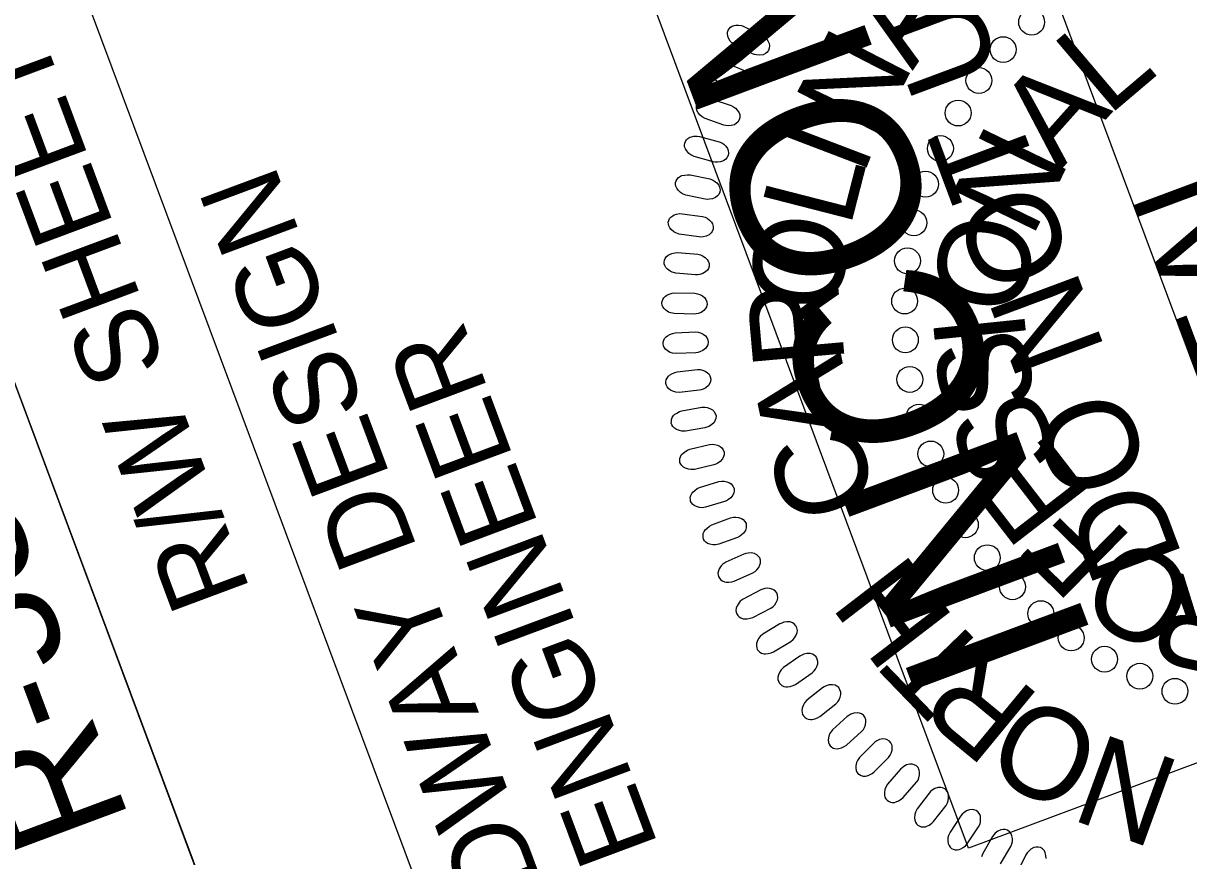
# Model space of a CAD drawing. Extents: x 477774 to 479389, y 493760 to 495720.
# Drawn here: x 477869.3 to 477941.5, y 495190.7 to 495242.3 of the extents above; entities that cross this region are included whole.
import ezdxf

# ---------------------------------------------------------------- set-up
doc = ezdxf.new("R2010")
doc.units = 0
for name, color, linetype in [('Sheet Data Field CELL', 7, 'Continuous'), ('Sheet PE Seal Cell', 7, 'Continuous'), ('Sheet Plan CELL', 7, 'Continuous'), ('Sheet Sticker Incomplete CELL', 7, 'Continuous')]:
    doc.layers.add(name, color=color, linetype=linetype)

msp = doc.modelspace()

# ---------------------------------------------------------------- linework, layer by layer
at = {"layer": 'Sheet PE Seal Cell'}
for points in [[(477914.47, 495240.395), (477913.371, 495240.94), (477913.191, 495241.071), (477913.088, 495241.179), (477912.986, 495241.355), (477912.931, 495241.491), (477912.91, 495241.626), (477912.92, 495241.738), (477912.952, 495241.848), (477913.02, 495241.939), (477913.1, 495242.033), (477913.2, 495242.101), (477913.335, 495242.15), (477913.434, 495242.168), (477913.597, 495242.162), (477913.785, 495242.136), (477913.938, 495242.085), (477915.067, 495241.534), (477915.209, 495241.439), (477915.314, 495241.337), (477915.417, 495241.186), (477915.493, 495241.023), (477915.522, 495240.9), (477915.505, 495240.733), (477915.457, 495240.59), (477915.355, 495240.474), (477915.264, 495240.402), (477915.118, 495240.333), (477914.913, 495240.301), (477914.722, 495240.32), (477914.592, 495240.351)], [(477913.494, 495238.169), (477912.362, 495238.643), (477912.174, 495238.762), (477912.065, 495238.865), (477911.952, 495239.034), (477911.889, 495239.166), (477911.858, 495239.3), (477911.862, 495239.412), (477911.887, 495239.523), (477911.949, 495239.619), (477912.023, 495239.717), (477912.118, 495239.791), (477912.251, 495239.849), (477912.348, 495239.873), (477912.512, 495239.877), (477912.7, 495239.863), (477912.856, 495239.822), (477914.018, 495239.343), (477914.165, 495239.257), (477914.277, 495239.161), (477914.389, 495239.017), (477914.475, 495238.86), (477914.511, 495238.739), (477914.505, 495238.571), (477914.466, 495238.425), (477914.371, 495238.303), (477914.285, 495238.226), (477914.144, 495238.147), (477913.941, 495238.103), (477913.75, 495238.11), (477913.619, 495238.133)], [(477912.695, 495235.98), (477911.536, 495236.382), (477911.341, 495236.489), (477911.226, 495236.584), (477911.102, 495236.746), (477911.03, 495236.874), (477910.992, 495237.006), (477910.989, 495237.117), (477911.007, 495237.231), (477911.062, 495237.329), (477911.13, 495237.433), (477911.221, 495237.512), (477911.349, 495237.578), (477911.444, 495237.609), (477911.608, 495237.622), (477911.797, 495237.621), (477911.955, 495237.59), (477913.144, 495237.184), (477913.297, 495237.108), (477913.415, 495237.019), (477913.535, 495236.882), (477913.631, 495236.73), (477913.675, 495236.612), (477913.68, 495236.444), (477913.649, 495236.297), (477913.562, 495236.168), (477913.481, 495236.086), (477913.345, 495235.999), (477913.146, 495235.942), (477912.954, 495235.937), (477912.822, 495235.952)], [(477912.03, 495233.709), (477910.849, 495234.038), (477910.647, 495234.133), (477910.526, 495234.221), (477910.393, 495234.374), (477910.313, 495234.497), (477910.266, 495234.626), (477910.256, 495234.739), (477910.267, 495234.852), (477910.316, 495234.954), (477910.377, 495235.061), (477910.463, 495235.146), (477910.587, 495235.22), (477910.68, 495235.257), (477910.842, 495235.282), (477911.031, 495235.291), (477911.191, 495235.27), (477912.403, 495234.94), (477912.561, 495234.873), (477912.683, 495234.792), (477912.813, 495234.663), (477912.918, 495234.518), (477912.968, 495234.402), (477912.984, 495234.235), (477912.963, 495234.086), (477912.885, 495233.952), (477912.808, 495233.865), (477912.678, 495233.769), (477912.483, 495233.7), (477912.292, 495233.683), (477912.159, 495233.689)], [(477911.536, 495231.391), (477910.337, 495231.645), (477910.13, 495231.727), (477910.004, 495231.807), (477909.861, 495231.951), (477909.774, 495232.069), (477909.719, 495232.195), (477909.702, 495232.306), (477909.706, 495232.42), (477909.748, 495232.526), (477909.803, 495232.636), (477909.882, 495232.726), (477910.002, 495232.808), (477910.092, 495232.85), (477910.253, 495232.885), (477910.441, 495232.906), (477910.601, 495232.895), (477911.832, 495232.642), (477911.993, 495232.585), (477912.12, 495232.512), (477912.258, 495232.392), (477912.372, 495232.253), (477912.43, 495232.142), (477912.456, 495231.975), (477912.444, 495231.825), (477912.374, 495231.687), (477912.303, 495231.595), (477912.18, 495231.491), (477911.989, 495231.41), (477911.8, 495231.381), (477911.666, 495231.379)], [(477911.146, 495229.048), (477909.933, 495229.226), (477909.721, 495229.295), (477909.59, 495229.367), (477909.439, 495229.503), (477909.345, 495229.615), (477909.282, 495229.737), (477909.257, 495229.847), (477909.254, 495229.96), (477909.29, 495230.068), (477909.337, 495230.182), (477909.411, 495230.277), (477909.525, 495230.366), (477909.613, 495230.414), (477909.77, 495230.459), (477909.957, 495230.492), (477910.118, 495230.491), (477911.363, 495230.316), (477911.527, 495230.269), (477911.659, 495230.204), (477911.803, 495230.093), (477911.925, 495229.961), (477911.99, 495229.854), (477912.027, 495229.689), (477912.025, 495229.539), (477911.964, 495229.396), (477911.899, 495229.3), (477911.782, 495229.189), (477911.597, 495229.095), (477911.409, 495229.055), (477911.276, 495229.044)], [(477910.938, 495226.703), (477909.715, 495226.805), (477909.5, 495226.86), (477909.365, 495226.924), (477909.205, 495227.05), (477909.104, 495227.155), (477909.034, 495227.274), (477909.003, 495227.382), (477908.992, 495227.495), (477909.022, 495227.605), (477909.061, 495227.722), (477909.129, 495227.821), (477909.238, 495227.917), (477909.322, 495227.97), (477909.477, 495228.025), (477909.66, 495228.069), (477909.821, 495228.079), (477911.074, 495227.982), (477911.241, 495227.946), (477911.377, 495227.889), (477911.529, 495227.787), (477911.658, 495227.663), (477911.73, 495227.56), (477911.777, 495227.398), (477911.784, 495227.248), (477911.732, 495227.103), (477911.673, 495227.002), (477911.563, 495226.884), (477911.385, 495226.779), (477911.2, 495226.726), (477911.069, 495226.708)], [(477910.846, 495224.277), (477909.62, 495224.301), (477909.401, 495224.343), (477909.263, 495224.398), (477909.095, 495224.514), (477908.988, 495224.613), (477908.91, 495224.727), (477908.873, 495224.832), (477908.854, 495224.945), (477908.877, 495225.056), (477908.909, 495225.175), (477908.972, 495225.279), (477909.073, 495225.382), (477909.154, 495225.44), (477909.305, 495225.504), (477909.485, 495225.561), (477909.645, 495225.58), (477910.902, 495225.562), (477911.071, 495225.535), (477911.21, 495225.488), (477911.367, 495225.395), (477911.505, 495225.281), (477911.583, 495225.182), (477911.639, 495225.023), (477911.656, 495224.873), (477911.613, 495224.725), (477911.562, 495224.621), (477911.459, 495224.496), (477911.287, 495224.38), (477911.107, 495224.316), (477910.976, 495224.289)], [(477910.957, 495221.881), (477909.731, 495221.828), (477909.51, 495221.856), (477909.368, 495221.903), (477909.194, 495222.007), (477909.081, 495222.1), (477908.996, 495222.208), (477908.952, 495222.311), (477908.927, 495222.422), (477908.942, 495222.535), (477908.967, 495222.656), (477909.022, 495222.764), (477909.117, 495222.872), (477909.194, 495222.935), (477909.341, 495223.009), (477909.518, 495223.076), (477909.676, 495223.105), (477910.931, 495223.166), (477911.102, 495223.152), (477911.243, 495223.112), (477911.407, 495223.03), (477911.551, 495222.923), (477911.634, 495222.83), (477911.701, 495222.676), (477911.727, 495222.527), (477911.694, 495222.376), (477911.648, 495222.27), (477911.555, 495222.138), (477911.39, 495222.012), (477911.214, 495221.936), (477911.085, 495221.901)], [(477911.16, 495219.555), (477909.941, 495219.426), (477909.719, 495219.44), (477909.574, 495219.477), (477909.393, 495219.571), (477909.274, 495219.656), (477909.183, 495219.759), (477909.133, 495219.859), (477909.1, 495219.968), (477909.109, 495220.082), (477909.126, 495220.204), (477909.174, 495220.314), (477909.263, 495220.428), (477909.335, 495220.496), (477909.477, 495220.579), (477909.649, 495220.658), (477909.806, 495220.698), (477911.055, 495220.837), (477911.226, 495220.832), (477911.369, 495220.802), (477911.537, 495220.73), (477911.688, 495220.633), (477911.778, 495220.545), (477911.854, 495220.395), (477911.889, 495220.249), (477911.865, 495220.096), (477911.827, 495219.987), (477911.741, 495219.85), (477911.585, 495219.713), (477911.413, 495219.627), (477911.288, 495219.584)], [(477911.523, 495217.23), (477910.314, 495217.024), (477910.091, 495217.024), (477909.945, 495217.053), (477909.759, 495217.135), (477909.634, 495217.212), (477909.537, 495217.309), (477909.48, 495217.405), (477909.441, 495217.513), (477909.442, 495217.627), (477909.452, 495217.75), (477909.493, 495217.863), (477909.574, 495217.983), (477909.642, 495218.055), (477909.779, 495218.146), (477909.946, 495218.236), (477910.1, 495218.285), (477911.337, 495218.503), (477911.508, 495218.508), (477911.653, 495218.488), (477911.825, 495218.426), (477911.982, 495218.339), (477912.077, 495218.257), (477912.162, 495218.112), (477912.207, 495217.968), (477912.192, 495217.814), (477912.161, 495217.702), (477912.084, 495217.561), (477911.937, 495217.414), (477911.771, 495217.317), (477911.648, 495217.266)], [(477912.072, 495214.938), (477910.878, 495214.657), (477910.656, 495214.643), (477910.509, 495214.662), (477910.318, 495214.732), (477910.188, 495214.802), (477910.085, 495214.893), (477910.022, 495214.985), (477909.977, 495215.09), (477909.971, 495215.204), (477909.973, 495215.326), (477910.007, 495215.442), (477910.08, 495215.567), (477910.144, 495215.643), (477910.274, 495215.744), (477910.436, 495215.842), (477910.585, 495215.901), (477911.807, 495216.196), (477911.977, 495216.213), (477912.123, 495216.202), (477912.299, 495216.151), (477912.461, 495216.074), (477912.56, 495215.998), (477912.655, 495215.858), (477912.709, 495215.718), (477912.704, 495215.563), (477912.68, 495215.45), (477912.612, 495215.303), (477912.474, 495215.147), (477912.314, 495215.041), (477912.195, 495214.982)], [(477912.735, 495212.664), (477911.56, 495212.308), (477911.34, 495212.28), (477911.191, 495212.29), (477910.996, 495212.348), (477910.863, 495212.409), (477910.754, 495212.493), (477910.686, 495212.582), (477910.634, 495212.684), (477910.621, 495212.796), (477910.615, 495212.92), (477910.642, 495213.037), (477910.706, 495213.166), (477910.766, 495213.246), (477910.889, 495213.354), (477911.044, 495213.463), (477911.189, 495213.531), (477912.391, 495213.902), (477912.559, 495213.931), (477912.706, 495213.928), (477912.884, 495213.888), (477913.05, 495213.821), (477913.155, 495213.752), (477913.258, 495213.619), (477913.321, 495213.481), (477913.326, 495213.327), (477913.308, 495213.212), (477913.249, 495213.061), (477913.122, 495212.898), (477912.97, 495212.781), (477912.854, 495212.715)], [(477913.535, 495210.444), (477912.386, 495210.015), (477912.167, 495209.974), (477912.017, 495209.974), (477911.819, 495210.02), (477911.683, 495210.073), (477911.569, 495210.15), (477911.495, 495210.234), (477911.437, 495210.332), (477911.417, 495210.444), (477911.403, 495210.566), (477911.422, 495210.685), (477911.479, 495210.818), (477911.533, 495210.902), (477911.65, 495211.017), (477911.797, 495211.137), (477911.939, 495211.213), (477913.113, 495211.659), (477913.28, 495211.698), (477913.427, 495211.704), (477913.607, 495211.676), (477913.778, 495211.62), (477913.886, 495211.556), (477913.997, 495211.43), (477914.068, 495211.297), (477914.083, 495211.143), (477914.073, 495211.028), (477914.024, 495210.873), (477913.906, 495210.702), (477913.762, 495210.577), (477913.651, 495210.503)], [(477913.933, 495209.402), (477912.813, 495208.902), (477912.628, 495208.779), (477912.522, 495208.674), (477912.412, 495208.502), (477912.352, 495208.369), (477912.325, 495208.234), (477912.331, 495208.123), (477912.359, 495208.012), (477912.423, 495207.918), (477912.498, 495207.821), (477912.595, 495207.749), (477912.73, 495207.694), (477912.827, 495207.673), (477912.991, 495207.672), (477913.179, 495207.69), (477913.334, 495207.735), (477914.484, 495208.24), (477914.63, 495208.33), (477914.739, 495208.428), (477914.849, 495208.574), (477914.93, 495208.734), (477914.964, 495208.855), (477914.954, 495209.023), (477914.912, 495209.168), (477914.814, 495209.288), (477914.726, 495209.363), (477914.583, 495209.438), (477914.38, 495209.479), (477914.188, 495209.467), (477914.057, 495209.442)], [(477914.976, 495207.189), (477913.889, 495206.619), (477913.712, 495206.485), (477913.613, 495206.373), (477913.514, 495206.195), (477913.463, 495206.058), (477913.444, 495205.922), (477913.457, 495205.811), (477913.491, 495205.702), (477913.561, 495205.612), (477913.643, 495205.52), (477913.745, 495205.455), (477913.882, 495205.409), (477913.98, 495205.393), (477914.144, 495205.403), (477914.331, 495205.433), (477914.482, 495205.487), (477915.599, 495206.064), (477915.739, 495206.162), (477915.842, 495206.267), (477915.941, 495206.42), (477916.013, 495206.584), (477916.038, 495206.707), (477916.019, 495206.874), (477915.967, 495207.016), (477915.862, 495207.13), (477915.769, 495207.2), (477915.622, 495207.266), (477915.417, 495207.293), (477915.226, 495207.269), (477915.098, 495207.235)], [(477916.153, 495205.087), (477915.105, 495204.451), (477914.937, 495204.305), (477914.844, 495204.188), (477914.757, 495204.003), (477914.714, 495203.864), (477914.704, 495203.727), (477914.724, 495203.617), (477914.765, 495203.51), (477914.84, 495203.424), (477914.928, 495203.338), (477915.033, 495203.279), (477915.173, 495203.241), (477915.273, 495203.232), (477915.435, 495203.252), (477915.619, 495203.294), (477915.768, 495203.357), (477916.846, 495204.003), (477916.979, 495204.11), (477917.075, 495204.221), (477917.165, 495204.38), (477917.226, 495204.549), (477917.244, 495204.673), (477917.214, 495204.839), (477917.153, 495204.976), (477917.041, 495205.084), (477916.945, 495205.147), (477916.794, 495205.204), (477916.587, 495205.219), (477916.398, 495205.183), (477916.272, 495205.141)], [(477917.402, 495203.092), (477916.395, 495202.391), (477916.237, 495202.235), (477916.151, 495202.112), (477916.077, 495201.923), (477916.042, 495201.781), (477916.041, 495201.643), (477916.067, 495201.534), (477916.115, 495201.431), (477916.196, 495201.35), (477916.289, 495201.27), (477916.398, 495201.218), (477916.539, 495201.189), (477916.639, 495201.185), (477916.8, 495201.216), (477916.981, 495201.269), (477917.125, 495201.342), (477918.161, 495202.054), (477918.287, 495202.169), (477918.376, 495202.286), (477918.456, 495202.451), (477918.506, 495202.622), (477918.516, 495202.747), (477918.476, 495202.911), (477918.407, 495203.045), (477918.289, 495203.145), (477918.188, 495203.202), (477918.033, 495203.249), (477917.826, 495203.25), (477917.64, 495203.203), (477917.517, 495203.154)], [(477918.799, 495201.123), (477917.839, 495200.36), (477917.69, 495200.195), (477917.613, 495200.067), (477917.55, 495199.874), (477917.524, 495199.729), (477917.532, 495199.592), (477917.565, 495199.485), (477917.62, 495199.385), (477917.705, 495199.309), (477917.803, 495199.235), (477917.914, 495199.189), (477918.058, 495199.169), (477918.158, 495199.172), (477918.317, 495199.212), (477918.494, 495199.277), (477918.634, 495199.359), (477919.622, 495200.134), (477919.741, 495200.258), (477919.822, 495200.379), (477919.892, 495200.549), (477919.931, 495200.723), (477919.933, 495200.849), (477919.882, 495201.01), (477919.805, 495201.139), (477919.681, 495201.231), (477919.576, 495201.282), (477919.42, 495201.32), (477919.212, 495201.308), (477919.03, 495201.249), (477918.91, 495201.192)], [(477920.334, 495199.347), (477919.423, 495198.525), (477919.285, 495198.35), (477919.216, 495198.218), (477919.165, 495198.021), (477919.149, 495197.875), (477919.165, 495197.739), (477919.205, 495197.634), (477919.266, 495197.538), (477919.356, 495197.468), (477919.458, 495197.399), (477919.573, 495197.361), (477919.717, 495197.35), (477919.816, 495197.359), (477919.972, 495197.41), (477920.145, 495197.486), (477920.279, 495197.575), (477921.217, 495198.412), (477921.328, 495198.542), (477921.401, 495198.669), (477921.46, 495198.842), (477921.489, 495199.019), (477921.483, 495199.145), (477921.422, 495199.301), (477921.336, 495199.426), (477921.207, 495199.509), (477921.1, 495199.554), (477920.94, 495199.582), (477920.734, 495199.558), (477920.556, 495199.487), (477920.44, 495199.422)], [(477921.948, 495197.689), (477921.09, 495196.812), (477920.964, 495196.629), (477920.904, 495196.492), (477920.865, 495196.293), (477920.858, 495196.146), (477920.883, 495196.011), (477920.93, 495195.909), (477920.996, 495195.817), (477921.09, 495195.752), (477921.196, 495195.69), (477921.313, 495195.66), (477921.458, 495195.658), (477921.556, 495195.673), (477921.709, 495195.733), (477921.877, 495195.82), (477922.005, 495195.918), (477922.888, 495196.811), (477922.991, 495196.948), (477923.056, 495197.08), (477923.103, 495197.256), (477923.121, 495197.435), (477923.107, 495197.559), (477923.037, 495197.712), (477922.944, 495197.831), (477922.809, 495197.907), (477922.699, 495197.944), (477922.539, 495197.962), (477922.335, 495197.925), (477922.161, 495197.843), (477922.049, 495197.771)], [(477923.627, 495196.092), (477922.826, 495195.162), (477922.71, 495194.972), (477922.659, 495194.832), (477922.633, 495194.631), (477922.635, 495194.484), (477922.668, 495194.35), (477922.721, 495194.252), (477922.794, 495194.163), (477922.891, 495194.105), (477923.001, 495194.05), (477923.12, 495194.027), (477923.264, 495194.034), (477923.362, 495194.056), (477923.51, 495194.125), (477923.673, 495194.222), (477923.794, 495194.328), (477924.62, 495195.276), (477924.714, 495195.418), (477924.77, 495195.553), (477924.807, 495195.732), (477924.813, 495195.912), (477924.792, 495196.036), (477924.712, 495196.184), (477924.612, 495196.296), (477924.472, 495196.364), (477924.36, 495196.394), (477924.199, 495196.402), (477923.998, 495196.351), (477923.829, 495196.259), (477923.722, 495196.18)], [(477925.402, 495194.601), (477924.661, 495193.624), (477924.558, 495193.426), (477924.516, 495193.283), (477924.502, 495193.08), (477924.514, 495192.934), (477924.555, 495192.803), (477924.614, 495192.708), (477924.692, 495192.624), (477924.793, 495192.572), (477924.906, 495192.524), (477925.026, 495192.508), (477925.169, 495192.525), (477925.265, 495192.552), (477925.41, 495192.631), (477925.565, 495192.738), (477925.68, 495192.852), (477926.445, 495193.849), (477926.529, 495193.997), (477926.578, 495194.136), (477926.602, 495194.317), (477926.598, 495194.496), (477926.569, 495194.618), (477926.479, 495194.761), (477926.372, 495194.867), (477926.229, 495194.926), (477926.115, 495194.949), (477925.954, 495194.947), (477925.756, 495194.883), (477925.594, 495194.78), (477925.492, 495194.696)], [(477927.371, 495193.201), (477926.693, 495192.178), (477926.602, 495191.975), (477926.568, 495191.83), (477926.568, 495191.626), (477926.589, 495191.481), (477926.638, 495191.353), (477926.704, 495191.261), (477926.786, 495191.183), (477926.89, 495191.138), (477927.006, 495191.096), (477927.127, 495191.088), (477927.269, 495191.114), (477927.363, 495191.147), (477927.502, 495191.235), (477927.651, 495191.351), (477927.758, 495191.472), (477928.459, 495192.515), (477928.533, 495192.669), (477928.574, 495192.81), (477928.587, 495192.992), (477928.571, 495193.17), (477928.534, 495193.291), (477928.436, 495193.427), (477928.322, 495193.527), (477928.176, 495193.576), (477928.061, 495193.592), (477927.9, 495193.58), (477927.707, 495193.504), (477927.551, 495193.392), (477927.454, 495193.3)]]:
    msp.add_lwpolyline(points, close=True, dxfattribs=at)
for points in [[(477929.825, 495190.224), (477930.459, 495191.308), (477930.524, 495191.467), (477930.555, 495191.61), (477930.557, 495191.793), (477930.529, 495191.97), (477930.485, 495192.088), (477930.379, 495192.218), (477930.259, 495192.31), (477930.109, 495192.349), (477929.994, 495192.359), (477929.834, 495192.336), (477929.646, 495192.249), (477929.498, 495192.127), (477929.407, 495192.029), (477929.329, 495191.925), (477928.717, 495190.861), (477928.64, 495190.653)], [(477932.638, 495190.551), (477932.629, 495190.733), (477932.591, 495190.909), (477932.539, 495191.024), (477932.425, 495191.147), (477932.299, 495191.231), (477932.148, 495191.261), (477932.032, 495191.263), (477931.874, 495191.231), (477931.692, 495191.132), (477931.552, 495191), (477931.467, 495190.898), (477931.397, 495190.788), (477930.852, 495189.689)]]:
    msp.add_lwpolyline(points, dxfattribs=at)
for centre in [(477931.747, 495242.35), (477929.98, 495240.652), (477928.484, 495238.735), (477927.193, 495236.724), (477926.098, 495234.531), (477925.18, 495232.318), (477924.457, 495229.924), (477924.06, 495227.567), (477923.883, 495225.079), (477923.929, 495222.674), (477924.204, 495220.227), (477924.777, 495217.891), (477925.5, 495215.611), (477926.423, 495213.364), (477927.645, 495211.227), (477929.002, 495209.184), (477930.565, 495207.387), (477932.319, 495205.721), (477934.2, 495204.213), (477936.262, 495202.9), (477938.442, 495201.843), (477940.618, 495200.912)]:
    msp.add_circle(centre, 0.801, dxfattribs=at)
at = {"layer": 'Sheet Plan CELL'}
msp.add_line((477894.735, 495150.5), (477824.758, 495337.899), dxfattribs=at)
msp.add_line((477894.735, 495150.5), (477824.758, 495337.899), dxfattribs=at)
for points in [[(477871.231, 495141.727), (477801.276, 495329.174), (477824.758, 495337.899), (477894.735, 495150.5)], [(477906.434, 495154.867), (477871.446, 495248.6), (477976.855, 495287.945), (478011.814, 495194.215)]]:
    msp.add_lwpolyline(points, close=True, dxfattribs=at)
at = {"layer": 'Sheet Sticker Incomplete CELL'}
msp.add_lwpolyline([(477949.848, 495199.411), (477927.831, 495191.193), (477876.425, 495328.912), (477898.442, 495337.13)], close=True, dxfattribs=at)

# ---------------------------------------------------------------- texts
at = {"layer": 'Sheet Data Field CELL'}
msp.add_text('R-5861', height=7.5, rotation=110.46898, dxfattribs=at).set_placement((477875.968, 495192.876))
at = {"layer": 'Sheet PE Seal Cell'}
for s, height, rotation, p in [('A', 5.669, 56.1418, (477924.368, 495239.318)), ('N', 5.669, 62.63116, (477921.988, 495234.886)), ('L', 5.669, 40.29984, (477936.459, 495236.475)), ('A', 5.669, 48.23963, (477933.459, 495233.088)), ('I', 5.669, 69.12052, (477921.288, 495232.698)), ('N', 5.669, 64.11923, (477931.74, 495228.885)), ('SEAL', 6.2363, 110.45034, (477950.235, 495216.19)), ('L', 5.669, 75.60988, (477920.494, 495229.527)), ('O', 5.669, 82.09923, (477919.778, 495224.208)), ('O', 5.669, 79.99882, (477931.089, 495224.039)), ('R', 5.669, 95.07795, (477920.198, 495221.211)), ('I', 5.669, 95.87842, (477931.454, 495222.571)), ('S', 5.669, 103.81821, (477932.191, 495218.789)), ('A', 5.669, 101.5673, (477920.925, 495216.992)), ('S', 5.669, 111.75801, (477933.636, 495215.208)), ('C', 5.669, 108.05666, (477922.33, 495212.633)), ('E', 5.669, 127.63761, (477935.503, 495212.951)), ('F', 5.669, 135.5774, (477938.13, 495210.312)), ('O', 5.669, 151.457, (477942.363, 495207.947)), ('H', 5.669, 127.52473, (477927.069, 495205.323)), ('R', 5.669, 167.3366, (477945.348, 495207.231)), ('T', 5.669, 134.01408, (477929.501, 495202.838)), ('R', 5.669, 140.50344, (477932.425, 495200.491)), ('O', 5.669, 153.48216, (477936.478, 495198.295)), ('N', 5.669, 159.97151, (477941.166, 495196.472))]:
    msp.add_text(s, height=height, rotation=rotation, dxfattribs=at).set_placement(p)
at = {"layer": 'Sheet Plan CELL'}
for s, p in [('R/W SHEET NO.', (477883.409, 495207.114)), ('PROJECT REFERENCE NO.', (477871.642, 495165.576)), ('ROADWAY DESIGN', (477906.497, 495175.571)), ('ENGINEER', (477908.667, 495191.312))]:
    msp.add_text(s, height=5.0001, rotation=110.46898, dxfattribs=at).set_placement(p)
at = {"layer": 'Sheet Sticker Incomplete CELL'}
for s, height, p in [('INCOMPLETE PLANS', 11.52, (477935.756, 495203.705)), ('DO NOT USE FOR R/W ACQUISITION', 5.76, (477941.131, 495209.18))]:
    msp.add_text(s, height=height, rotation=110.46898, dxfattribs=at).set_placement(p)

doc.saveas('drawing.dxf')
